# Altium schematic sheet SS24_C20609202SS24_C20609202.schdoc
size 127 x 101 mm
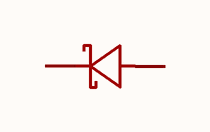
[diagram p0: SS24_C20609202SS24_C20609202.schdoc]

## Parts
D?  ss24_c20609202  [DO-214AC_L4.3-W2.7-LS5.2-RD]  (value not drawn)

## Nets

Not connected (* = marked no-connect by the designer): D? 1(C) 2(A)

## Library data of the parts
D? = ss24_c20609202: 二极管配置:独立式;正向压降(Vf):550mV@2A;直流反向耐压(Vr):40V;整流电流:2A;; Manufacturer: JSMSEMI(杰盛微); ManufacturerPart: SS24; AddInBom: yes; ModelId: 862b72d952ae4046a2a0ed3498f0d1d7; ModelTransform: 204.724,106.299,0,0,0,0,0,0,0; Diode Configuration: 独立式; Voltage - DC Reverse(Vr): 40V; Current - Rectified: 2A; Reverse Leakage Current (Ir): 5mA@40V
